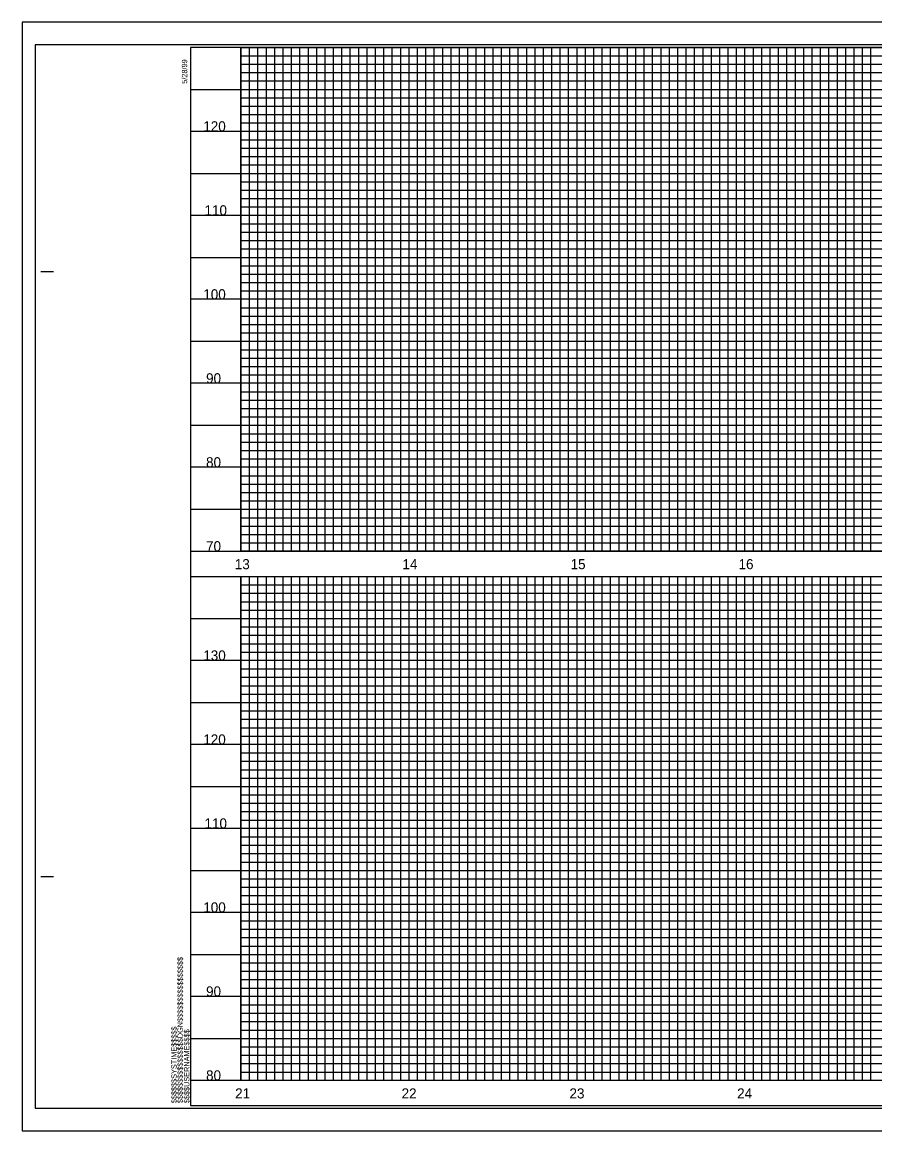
# Model space of a CAD drawing. Extents: x 2113883 to 2114903, y 714180 to 714840.
# Drawn here: x 2113883 to 2114390, y 714180 to 714840 of the extents above; entities that cross this region are included whole.
import ezdxf

# ---------------------------------------------------------------- set-up
doc = ezdxf.new("R2010")
doc.units = 0
for name, color, linetype in [('Exist Vertical Profile Horizontal Axis Label Major', 7, 'Continuous'), ('Exist Vertical Profile Vertical Axis Label', 7, 'Continuous'), ('Sheet Cutting Line CELL', 7, 'Continuous'), ('Sheet Layout Profile Border Port 1', 7, 'Continuous'), ('Sheet Layout Profile Border Port 2', 7, 'Continuous'), ('Sheet Plot Border Inside CELL', 7, 'Continuous'), ('Sheet Plot Border Outside CELL', 7, 'Continuous'), ('Sheet Profile CELL', 7, 'Continuous'), ('Sheet Profile Grid Major CELL', 7, 'Continuous'), ('Sheet Profile Grid Middle CELL', 7, 'Continuous'), ('Sheet Profile Grid Minor CELL', 7, 'Continuous')]:
    doc.layers.add(name, color=color, linetype=linetype)

msp = doc.modelspace()

# ---------------------------------------------------------------- linework, layer by layer
at = {"layer": 'Sheet Cutting Line CELL'}
for p, q in [((2114902.56, 714840.29), (2113882.56, 714840.29)), ((2113882.56, 714840.29), (2113882.56, 714180.29)), ((2113882.56, 714180.29), (2114902.56, 714180.29))]:
    msp.add_line(p, q, dxfattribs=at)
at = {"layer": 'Sheet Layout Profile Border Port 1'}
msp.add_lwpolyline([(2114012.76, 714825.29), (2114762.73, 714825.29), (2114762.73, 714705.41), (2114852.76, 714705.29), (2114852.76, 714525.29), (2114012.76, 714525.29)], close=True, dxfattribs=at)
at = {"layer": 'Sheet Layout Profile Border Port 2'}
msp.add_lwpolyline([(2114012.76, 714510.29), (2114852.76, 714510.29), (2114852.76, 714210.29), (2114012.76, 714210.29)], close=True, dxfattribs=at)
at = {"layer": 'Sheet Plot Border Inside CELL'}
msp.add_lwpolyline([(2113890.36, 714193.76), (2114890.26, 714193.76), (2114890.26, 714826.82), (2113890.36, 714826.82)], close=True, dxfattribs=at)
at = {"layer": 'Sheet Plot Border Outside CELL'}
msp.add_lwpolyline([(2113882.56, 714180.29), (2114902.56, 714180.29), (2114902.56, 714840.29), (2113882.56, 714840.29)], close=True, dxfattribs=at)
at = {"layer": 'Sheet Profile CELL'}
for p, q in [((2113893.66, 714691.79), (2113901.16, 714691.79)), ((2113982.76, 714525.29), (2114882.76, 714525.29)), ((2113982.76, 714510.29), (2114882.76, 714510.29)), ((2113893.66, 714331.79), (2113901.16, 714331.79)), ((2114882.76, 714210.29), (2113982.76, 714210.29)), ((2113982.76, 714195.29), (2114882.76, 714195.29)), ((2113982.76, 714195.29), (2113982.76, 714195.29)), ((2113982.76, 714195.29), (2113982.76, 714195.29)), ((2113982.76, 714195.29), (2113982.76, 714195.29)), ((2113982.76, 714195.29), (2113982.76, 714195.29)), ((2113982.76, 714195.29), (2113982.76, 714195.29)), ((2113982.76, 714195.29), (2113982.76, 714195.29)), ((2113982.76, 714195.29), (2113982.76, 714195.29))]:
    msp.add_line(p, q, dxfattribs=at)
msp.add_lwpolyline([(2114882.76, 714825.29), (2113982.76, 714825.29), (2113982.76, 714195.29), (2114882.76, 714195.29)], close=True, dxfattribs=at)
msp.add_lwpolyline([(2114005.26, 714195.29), (2114005.26, 714195.29)], dxfattribs=at)
at = {"layer": 'Sheet Profile Grid Major CELL'}
for p, q in [((2114012.76, 714825.29), (2114012.76, 714525.29)), ((2114037.76, 714825.29), (2114037.76, 714525.29)), ((2114062.76, 714825.29), (2114062.76, 714525.29)), ((2114087.76, 714825.29), (2114087.76, 714525.29)), ((2114112.76, 714825.29), (2114112.76, 714525.29)), ((2114137.76, 714825.29), (2114137.76, 714525.29)), ((2114162.76, 714825.29), (2114162.76, 714525.29)), ((2114187.76, 714825.29), (2114187.76, 714525.29)), ((2114212.76, 714825.29), (2114212.76, 714525.29)), ((2114237.76, 714825.29), (2114237.76, 714525.29)), ((2114262.76, 714825.29), (2114262.76, 714525.29)), ((2114287.76, 714825.29), (2114287.76, 714525.29)), ((2114312.76, 714825.29), (2114312.76, 714525.29)), ((2114337.76, 714825.29), (2114337.76, 714525.29)), ((2114362.76, 714825.29), (2114362.76, 714525.29)), ((2114387.76, 714825.29), (2114387.76, 714525.29)), ((2113982.76, 714800.29), (2114762.76, 714800.29)), ((2114762.76, 714775.29), (2113982.76, 714775.29)), ((2113982.76, 714750.29), (2114762.76, 714750.29)), ((2114762.76, 714725.29), (2113982.76, 714725.29)), ((2113982.76, 714700.29), (2114882.76, 714700.29)), ((2114882.76, 714675.29), (2113982.76, 714675.29)), ((2113982.76, 714650.29), (2114882.76, 714650.29)), ((2114882.76, 714625.29), (2113982.76, 714625.29)), ((2113982.76, 714600.29), (2114882.76, 714600.29)), ((2114882.76, 714575.29), (2113982.76, 714575.29)), ((2113982.76, 714550.29), (2114882.76, 714550.29)), ((2114012.76, 714510.29), (2114012.76, 714210.29)), ((2114037.76, 714510.29), (2114037.76, 714210.29)), ((2114062.76, 714510.29), (2114062.76, 714210.29)), ((2114087.76, 714510.29), (2114087.76, 714210.29)), ((2114112.76, 714510.29), (2114112.76, 714210.29)), ((2114137.76, 714510.29), (2114137.76, 714210.29)), ((2114162.76, 714510.29), (2114162.76, 714210.29)), ((2114187.76, 714510.29), (2114187.76, 714210.29)), ((2114212.76, 714510.29), (2114212.76, 714210.29)), ((2114237.76, 714510.29), (2114237.76, 714210.29)), ((2114262.76, 714510.29), (2114262.76, 714210.29)), ((2114287.76, 714510.29), (2114287.76, 714210.29)), ((2114312.76, 714510.29), (2114312.76, 714210.29)), ((2114337.76, 714510.29), (2114337.76, 714210.29)), ((2114362.76, 714510.29), (2114362.76, 714210.29)), ((2114387.76, 714510.29), (2114387.76, 714210.29)), ((2113982.76, 714485.29), (2114882.76, 714485.29)), ((2114882.76, 714460.29), (2113982.76, 714460.29)), ((2113982.76, 714435.29), (2114882.76, 714435.29)), ((2114882.76, 714410.29), (2113982.76, 714410.29)), ((2113982.76, 714385.29), (2114882.76, 714385.29)), ((2114882.76, 714360.29), (2113982.76, 714360.29)), ((2113982.76, 714335.29), (2114882.76, 714335.29)), ((2114882.76, 714310.29), (2113982.76, 714310.29)), ((2113982.76, 714285.29), (2114882.76, 714285.29)), ((2114882.76, 714260.29), (2113982.76, 714260.29)), ((2113982.76, 714235.29), (2114882.76, 714235.29))]:
    msp.add_line(p, q, dxfattribs=at)
at = {"layer": 'Sheet Profile Grid Middle CELL'}
for p, q in [((2114012.76, 714820.29), (2114762.76, 714820.29)), ((2114012.76, 714815.29), (2114762.76, 714815.29)), ((2114012.76, 714810.29), (2114762.76, 714810.29)), ((2114012.76, 714805.29), (2114762.76, 714805.29)), ((2114012.76, 714795.29), (2114762.76, 714795.29)), ((2114012.76, 714790.29), (2114762.76, 714790.29)), ((2114012.76, 714785.29), (2114762.76, 714785.29)), ((2114012.76, 714780.29), (2114762.76, 714780.29)), ((2114012.76, 714770.29), (2114762.76, 714770.29)), ((2114012.76, 714765.29), (2114762.76, 714765.29)), ((2114012.76, 714760.29), (2114762.76, 714760.29)), ((2114012.76, 714755.29), (2114762.76, 714755.29)), ((2114012.76, 714745.29), (2114762.76, 714745.29)), ((2114012.76, 714740.29), (2114762.76, 714740.29)), ((2114012.76, 714735.29), (2114762.76, 714735.29)), ((2114012.76, 714730.29), (2114762.76, 714730.29)), ((2114012.76, 714720.29), (2114762.76, 714720.29)), ((2114012.76, 714715.29), (2114762.76, 714715.29)), ((2114012.76, 714710.29), (2114762.76, 714710.29)), ((2114012.76, 714705.29), (2114852.76, 714705.29)), ((2114012.76, 714695.29), (2114852.76, 714695.29)), ((2114012.76, 714690.29), (2114852.76, 714690.29)), ((2114012.76, 714685.29), (2114852.76, 714685.29)), ((2114012.76, 714680.29), (2114852.76, 714680.29)), ((2114012.76, 714670.29), (2114852.76, 714670.29)), ((2114012.76, 714665.29), (2114852.76, 714665.29)), ((2114012.76, 714660.29), (2114852.76, 714660.29)), ((2114012.76, 714655.29), (2114852.76, 714655.29)), ((2114012.76, 714645.29), (2114852.76, 714645.29)), ((2114012.76, 714640.29), (2114852.76, 714640.29)), ((2114012.76, 714635.29), (2114852.76, 714635.29)), ((2114012.76, 714630.29), (2114852.76, 714630.29)), ((2114012.76, 714620.29), (2114852.76, 714620.29)), ((2114012.76, 714615.29), (2114852.76, 714615.29)), ((2114012.76, 714610.29), (2114852.76, 714610.29)), ((2114012.76, 714605.29), (2114852.76, 714605.29)), ((2114012.76, 714595.29), (2114852.76, 714595.29)), ((2114012.76, 714590.29), (2114852.76, 714590.29)), ((2114012.76, 714585.29), (2114852.76, 714585.29)), ((2114012.76, 714580.29), (2114852.76, 714580.29)), ((2114012.76, 714570.29), (2114852.76, 714570.29)), ((2114012.76, 714565.29), (2114852.76, 714565.29)), ((2114012.76, 714560.29), (2114852.76, 714560.29)), ((2114012.76, 714555.29), (2114852.76, 714555.29)), ((2114012.76, 714545.29), (2114852.76, 714545.29)), ((2114012.76, 714540.29), (2114852.76, 714540.29)), ((2114012.76, 714535.29), (2114852.76, 714535.29)), ((2114012.76, 714530.29), (2114852.76, 714530.29)), ((2114012.76, 714505.29), (2114852.76, 714505.29)), ((2114012.76, 714500.29), (2114852.76, 714500.29)), ((2114012.76, 714495.29), (2114852.76, 714495.29)), ((2114012.76, 714490.29), (2114852.76, 714490.29)), ((2114012.76, 714480.29), (2114852.76, 714480.29)), ((2114012.76, 714475.29), (2114852.76, 714475.29)), ((2114012.76, 714470.29), (2114852.76, 714470.29)), ((2114012.76, 714465.29), (2114852.76, 714465.29)), ((2114012.76, 714455.29), (2114852.76, 714455.29)), ((2114012.76, 714450.29), (2114852.76, 714450.29)), ((2114012.76, 714445.29), (2114852.76, 714445.29)), ((2114012.76, 714440.29), (2114852.76, 714440.29)), ((2114012.76, 714430.29), (2114852.76, 714430.29)), ((2114012.76, 714425.29), (2114852.76, 714425.29)), ((2114012.76, 714420.29), (2114852.76, 714420.29)), ((2114012.76, 714415.29), (2114852.76, 714415.29)), ((2114012.76, 714405.29), (2114852.76, 714405.29)), ((2114012.76, 714400.29), (2114852.76, 714400.29)), ((2114012.76, 714395.29), (2114852.76, 714395.29)), ((2114012.76, 714390.29), (2114852.76, 714390.29)), ((2114012.76, 714380.29), (2114852.76, 714380.29)), ((2114012.76, 714375.29), (2114852.76, 714375.29)), ((2114012.76, 714370.29), (2114852.76, 714370.29)), ((2114012.76, 714365.29), (2114852.76, 714365.29)), ((2114012.76, 714355.29), (2114852.76, 714355.29)), ((2114012.76, 714350.29), (2114852.76, 714350.29)), ((2114012.76, 714345.29), (2114852.76, 714345.29)), ((2114012.76, 714340.29), (2114852.76, 714340.29)), ((2114012.76, 714330.29), (2114852.76, 714330.29)), ((2114012.76, 714325.29), (2114852.76, 714325.29)), ((2114012.76, 714320.29), (2114852.76, 714320.29)), ((2114012.76, 714315.29), (2114852.76, 714315.29)), ((2114012.76, 714305.29), (2114852.76, 714305.29)), ((2114012.76, 714300.29), (2114852.76, 714300.29)), ((2114012.76, 714295.29), (2114852.76, 714295.29)), ((2114012.76, 714290.29), (2114852.76, 714290.29)), ((2114012.76, 714280.29), (2114852.76, 714280.29)), ((2114012.76, 714275.29), (2114852.76, 714275.29)), ((2114012.76, 714270.29), (2114852.76, 714270.29)), ((2114012.76, 714265.29), (2114852.76, 714265.29)), ((2114012.76, 714255.29), (2114852.76, 714255.29)), ((2114012.76, 714250.29), (2114852.76, 714250.29)), ((2114012.76, 714245.29), (2114852.76, 714245.29)), ((2114012.76, 714240.29), (2114852.76, 714240.29)), ((2114012.76, 714230.29), (2114852.76, 714230.29)), ((2114012.76, 714225.29), (2114852.76, 714225.29)), ((2114012.76, 714220.29), (2114852.76, 714220.29)), ((2114012.76, 714215.29), (2114852.76, 714215.29))]:
    msp.add_line(p, q, dxfattribs=at)
at = {"layer": 'Sheet Profile Grid Minor CELL'}
for p, q in [((2114017.76, 714825.29), (2114017.76, 714525.29)), ((2114022.76, 714825.29), (2114022.76, 714525.29)), ((2114027.76, 714825.29), (2114027.76, 714525.29)), ((2114032.76, 714825.29), (2114032.76, 714525.29)), ((2114042.76, 714825.29), (2114042.76, 714525.29)), ((2114047.76, 714825.29), (2114047.76, 714525.29)), ((2114052.76, 714825.29), (2114052.76, 714525.29)), ((2114057.76, 714825.29), (2114057.76, 714525.29)), ((2114067.76, 714825.29), (2114067.76, 714525.29)), ((2114072.76, 714825.29), (2114072.76, 714525.29)), ((2114077.76, 714825.29), (2114077.76, 714525.29)), ((2114082.76, 714825.29), (2114082.76, 714525.29)), ((2114092.76, 714825.29), (2114092.76, 714525.29)), ((2114097.76, 714825.29), (2114097.76, 714525.29)), ((2114102.76, 714825.29), (2114102.76, 714525.29)), ((2114107.76, 714825.29), (2114107.76, 714525.29)), ((2114117.76, 714825.29), (2114117.76, 714525.29)), ((2114122.76, 714825.29), (2114122.76, 714525.29)), ((2114127.76, 714825.29), (2114127.76, 714525.29)), ((2114132.76, 714825.29), (2114132.76, 714525.29)), ((2114142.76, 714825.29), (2114142.76, 714525.29)), ((2114147.76, 714825.29), (2114147.76, 714525.29)), ((2114152.76, 714825.29), (2114152.76, 714525.29)), ((2114157.76, 714825.29), (2114157.76, 714525.29)), ((2114167.76, 714825.29), (2114167.76, 714525.29)), ((2114172.76, 714825.29), (2114172.76, 714525.29)), ((2114177.76, 714825.29), (2114177.76, 714525.29)), ((2114182.76, 714825.29), (2114182.76, 714525.29)), ((2114192.76, 714825.29), (2114192.76, 714525.29)), ((2114197.76, 714825.29), (2114197.76, 714525.29)), ((2114202.76, 714825.29), (2114202.76, 714525.29)), ((2114207.76, 714825.29), (2114207.76, 714525.29)), ((2114217.76, 714825.29), (2114217.76, 714525.29)), ((2114222.76, 714825.29), (2114222.76, 714525.29)), ((2114227.76, 714825.29), (2114227.76, 714525.29)), ((2114232.76, 714825.29), (2114232.76, 714525.29)), ((2114242.76, 714825.29), (2114242.76, 714525.29)), ((2114247.76, 714825.29), (2114247.76, 714525.29)), ((2114252.76, 714825.29), (2114252.76, 714525.29)), ((2114257.76, 714825.29), (2114257.76, 714525.29)), ((2114267.76, 714825.29), (2114267.76, 714525.29)), ((2114272.76, 714825.29), (2114272.76, 714525.29)), ((2114277.76, 714825.29), (2114277.76, 714525.29)), ((2114282.76, 714825.29), (2114282.76, 714525.29)), ((2114292.76, 714825.29), (2114292.76, 714525.29)), ((2114297.76, 714825.29), (2114297.76, 714525.29)), ((2114302.76, 714825.29), (2114302.76, 714525.29)), ((2114307.76, 714825.29), (2114307.76, 714525.29)), ((2114317.76, 714825.29), (2114317.76, 714525.29)), ((2114322.76, 714825.29), (2114322.76, 714525.29)), ((2114327.76, 714825.29), (2114327.76, 714525.29)), ((2114332.76, 714825.29), (2114332.76, 714525.29)), ((2114342.76, 714825.29), (2114342.76, 714525.29)), ((2114347.76, 714825.29), (2114347.76, 714525.29)), ((2114352.76, 714825.29), (2114352.76, 714525.29)), ((2114357.76, 714825.29), (2114357.76, 714525.29)), ((2114367.76, 714825.29), (2114367.76, 714525.29)), ((2114372.76, 714825.29), (2114372.76, 714525.29)), ((2114377.76, 714825.29), (2114377.76, 714525.29)), ((2114382.76, 714825.29), (2114382.76, 714525.29)), ((2114012.76, 714819.29), (2114012.76, 714819.29)), ((2114017.76, 714510.29), (2114017.76, 714210.29)), ((2114022.76, 714510.29), (2114022.76, 714210.29)), ((2114027.76, 714510.29), (2114027.76, 714210.29)), ((2114032.76, 714510.29), (2114032.76, 714210.29)), ((2114042.76, 714510.29), (2114042.76, 714210.29)), ((2114047.76, 714510.29), (2114047.76, 714210.29)), ((2114052.76, 714510.29), (2114052.76, 714210.29)), ((2114057.76, 714510.29), (2114057.76, 714210.29)), ((2114067.76, 714510.29), (2114067.76, 714210.29)), ((2114072.76, 714510.29), (2114072.76, 714210.29)), ((2114077.76, 714510.29), (2114077.76, 714210.29)), ((2114082.76, 714510.29), (2114082.76, 714210.29)), ((2114092.76, 714510.29), (2114092.76, 714210.29)), ((2114097.76, 714510.29), (2114097.76, 714210.29)), ((2114102.76, 714510.29), (2114102.76, 714210.29)), ((2114107.76, 714510.29), (2114107.76, 714210.29)), ((2114117.76, 714510.29), (2114117.76, 714210.29)), ((2114122.76, 714510.29), (2114122.76, 714210.29)), ((2114127.76, 714510.29), (2114127.76, 714210.29)), ((2114132.76, 714510.29), (2114132.76, 714210.29)), ((2114142.76, 714510.29), (2114142.76, 714210.29)), ((2114147.76, 714510.29), (2114147.76, 714210.29)), ((2114152.76, 714510.29), (2114152.76, 714210.29)), ((2114157.76, 714510.29), (2114157.76, 714210.29)), ((2114167.76, 714510.29), (2114167.76, 714210.29)), ((2114172.76, 714510.29), (2114172.76, 714210.29)), ((2114177.76, 714510.29), (2114177.76, 714210.29)), ((2114182.76, 714510.29), (2114182.76, 714210.29)), ((2114192.76, 714510.29), (2114192.76, 714210.29)), ((2114197.76, 714510.29), (2114197.76, 714210.29)), ((2114202.76, 714510.29), (2114202.76, 714210.29)), ((2114207.76, 714510.29), (2114207.76, 714210.29)), ((2114217.76, 714510.29), (2114217.76, 714210.29)), ((2114222.76, 714510.29), (2114222.76, 714210.29)), ((2114227.76, 714510.29), (2114227.76, 714210.29)), ((2114232.76, 714510.29), (2114232.76, 714210.29)), ((2114242.76, 714510.29), (2114242.76, 714210.29)), ((2114247.76, 714510.29), (2114247.76, 714210.29)), ((2114252.76, 714510.29), (2114252.76, 714210.29)), ((2114257.76, 714510.29), (2114257.76, 714210.29)), ((2114267.76, 714510.29), (2114267.76, 714210.29)), ((2114272.76, 714510.29), (2114272.76, 714210.29)), ((2114277.76, 714510.29), (2114277.76, 714210.29)), ((2114282.76, 714510.29), (2114282.76, 714210.29)), ((2114292.76, 714510.29), (2114292.76, 714210.29)), ((2114297.76, 714510.29), (2114297.76, 714210.29)), ((2114302.76, 714510.29), (2114302.76, 714210.29)), ((2114307.76, 714510.29), (2114307.76, 714210.29)), ((2114317.76, 714510.29), (2114317.76, 714210.29)), ((2114322.76, 714510.29), (2114322.76, 714210.29)), ((2114327.76, 714510.29), (2114327.76, 714210.29)), ((2114332.76, 714510.29), (2114332.76, 714210.29)), ((2114342.76, 714510.29), (2114342.76, 714210.29)), ((2114347.76, 714510.29), (2114347.76, 714210.29)), ((2114352.76, 714510.29), (2114352.76, 714210.29)), ((2114357.76, 714510.29), (2114357.76, 714210.29)), ((2114367.76, 714510.29), (2114367.76, 714210.29)), ((2114372.76, 714510.29), (2114372.76, 714210.29)), ((2114377.76, 714510.29), (2114377.76, 714210.29)), ((2114382.76, 714510.29), (2114382.76, 714210.29)), ((2114012.76, 714504.29), (2114012.76, 714504.29))]:
    msp.add_line(p, q, dxfattribs=at)

# ---------------------------------------------------------------- texts
at = {"layer": 'Exist Vertical Profile Horizontal Axis Label Major'}
for s, p in [('13', (2114009.17, 714514.63)), ('13', (2114009.17, 714514.63)), ('13', (2114009.17, 714514.63)), ('14', (2114108.99, 714514.63)), ('14', (2114108.99, 714514.63)), ('14', (2114108.99, 714514.63)), ('15', (2114209.11, 714514.63)), ('15', (2114209.11, 714514.63)), ('15', (2114209.11, 714514.63)), ('16', (2114309.12, 714514.63)), ('16', (2114309.12, 714514.63)), ('16', (2114309.12, 714514.63)), ('21', (2114009.36, 714199.56)), ('21', (2114009.36, 714199.56)), ('21', (2114009.36, 714199.56)), ('21', (2114009.36, 714199.56)), ('22', (2114108.48, 714199.56)), ('22', (2114108.48, 714199.56)), ('22', (2114108.48, 714199.56)), ('22', (2114108.48, 714199.56)), ('23', (2114208.45, 714199.56)), ('23', (2114208.45, 714199.56)), ('23', (2114208.45, 714199.56)), ('23', (2114208.45, 714199.56)), ('24', (2114308.27, 714199.56)), ('24', (2114308.27, 714199.56)), ('24', (2114308.27, 714199.56)), ('24', (2114308.27, 714199.56))]:
    msp.add_text(s, height=6, dxfattribs=at).set_placement(p)
at = {"layer": 'Exist Vertical Profile Vertical Axis Label'}
for s, p in [('120', (2113990.4, 714775.29)), ('110', (2113991.12, 714725.29)), ('100', (2113990.4, 714675.29)), ('90', (2113992.06, 714625.29)), ('80', (2113992.06, 714575.29)), ('70', (2113992.06, 714525.29)), ('130', (2113990.4, 714460.29)), ('130', (2113990.4, 714460.29)), ('130', (2113990.4, 714460.29)), ('130', (2113990.4, 714460.29)), ('130', (2113990.4, 714460.29)), ('120', (2113990.4, 714410.29)), ('120', (2113990.4, 714410.29)), ('120', (2113990.4, 714410.29)), ('120', (2113990.4, 714410.29)), ('120', (2113990.4, 714410.29)), ('110', (2113991.12, 714360.29)), ('110', (2113991.12, 714360.29)), ('110', (2113991.12, 714360.29)), ('110', (2113991.12, 714360.29)), ('110', (2113991.12, 714360.29)), ('100', (2113990.4, 714310.29)), ('100', (2113990.4, 714310.29)), ('100', (2113990.4, 714310.29)), ('100', (2113990.4, 714310.29)), ('100', (2113990.4, 714310.29)), ('90', (2113992.06, 714260.29)), ('90', (2113992.06, 714260.29)), ('90', (2113992.06, 714260.29)), ('90', (2113992.06, 714260.29)), ('90', (2113992.06, 714260.29)), ('80', (2113992.06, 714210.29))]:
    msp.add_text(s, height=6, dxfattribs=at).set_placement(p)
at = {"layer": 'Sheet Profile CELL'}
for s, p in [('5/28/99', (2113980.82, 714803.63)), ('$$$$$$$$$$$$$$$$DGN$$$$$$$$$$$$$$$$', (2113978.18, 714196.71)), ('$$$$$$SYSTIME$$$$$', (2113974.55, 714196.71)), ('$$$$USERNAME$$$$', (2113982.13, 714196.72))]:
    msp.add_text(s, height=3.15, rotation=90, dxfattribs=at).set_placement(p)

doc.saveas('drawing.dxf')
